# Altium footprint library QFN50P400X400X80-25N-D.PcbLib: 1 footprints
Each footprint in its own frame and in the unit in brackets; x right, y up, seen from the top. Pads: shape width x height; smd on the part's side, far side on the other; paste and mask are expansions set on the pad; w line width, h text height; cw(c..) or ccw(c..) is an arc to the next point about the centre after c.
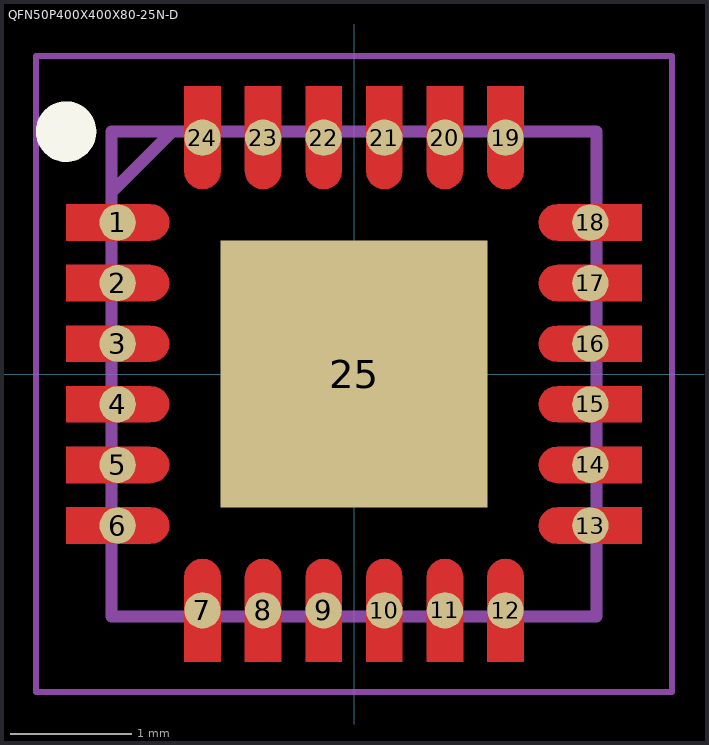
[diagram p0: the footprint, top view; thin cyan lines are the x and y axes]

## QFN50P400X400X80-25N-D [mm]
pads (25):
  round 0.3 smd: 1(-1.95,1.25) 2(-1.95,0.75) 3(-1.95,0.25) 4(-1.95,-0.25) 5(-1.95,-0.75) 6(-1.95,-1.25) 7(-1.25,-1.95) 8(-0.75,-1.95) 9(-0.25,-1.95) 10(0.25,-1.95) 11(0.75,-1.95) 12(1.25,-1.95) 13(1.95,-1.25) 14(1.95,-0.75) 15(1.95,-0.25) 16(1.95,0.25) 17(1.95,0.75) 18(1.95,1.25) 19(1.25,1.95) 20(0.75,1.95) 21(0.25,1.95) 22(-0.25,1.95) 23(-0.75,1.95) 24(-1.25,1.95)
  rect 2.2x2.2 smd: 25(0,0)
L1-Top Layer:
  region: -2.375,1.4 -1.675,1.4 -1.636,1.395 -1.6,1.38 -1.569,1.356 -1.545,1.325 -1.53,1.289 -1.525,1.25 -1.53,1.211 -1.545,1.175 -1.569,1.144 -1.6,1.12 -1.636,1.105 -1.675,1.1 -2.375,1.1
  region: -2.375,0.9 -1.675,0.9 -1.636,0.895 -1.6,0.88 -1.569,0.856 -1.545,0.825 -1.53,0.789 -1.525,0.75 -1.53,0.711 -1.545,0.675 -1.569,0.644 -1.6,0.62 -1.636,0.605 -1.675,0.6 -2.375,0.6
  region: -2.375,0.4 -1.675,0.4 -1.636,0.395 -1.6,0.38 -1.569,0.356 -1.545,0.325 -1.53,0.289 -1.525,0.25 -1.53,0.211 -1.545,0.175 -1.569,0.144 -1.6,0.12 -1.636,0.105 -1.675,0.1 -2.375,0.1
  region: -2.375,-0.1 -1.675,-0.1 -1.636,-0.105 -1.6,-0.12 -1.569,-0.144 -1.545,-0.175 -1.53,-0.211 -1.525,-0.25 -1.53,-0.289 -1.545,-0.325 -1.569,-0.356 -1.6,-0.38 -1.636,-0.395 -1.675,-0.4 -2.375,-0.4
  region: -2.375,-0.6 -1.675,-0.6 -1.636,-0.605 -1.6,-0.62 -1.569,-0.644 -1.545,-0.675 -1.53,-0.711 -1.525,-0.75 -1.53,-0.789 -1.545,-0.825 -1.569,-0.856 -1.6,-0.88 -1.636,-0.895 -1.675,-0.9 -2.375,-0.9
  region: -2.375,-1.1 -1.675,-1.1 -1.636,-1.105 -1.6,-1.12 -1.569,-1.144 -1.545,-1.175 -1.53,-1.211 -1.525,-1.25 -1.53,-1.289 -1.545,-1.325 -1.569,-1.356 -1.6,-1.38 -1.636,-1.395 -1.675,-1.4 -2.375,-1.4
  region: -1.4,-2.375 -1.4,-1.675 -1.395,-1.636 -1.38,-1.6 -1.356,-1.569 -1.325,-1.545 -1.289,-1.53 -1.25,-1.525 -1.211,-1.53 -1.175,-1.545 -1.144,-1.569 -1.12,-1.6 -1.105,-1.636 -1.1,-1.675 -1.1,-2.375
  region: -0.9,-2.375 -0.9,-1.675 -0.895,-1.636 -0.88,-1.6 -0.856,-1.569 -0.825,-1.545 -0.789,-1.53 -0.75,-1.525 -0.711,-1.53 -0.675,-1.545 -0.644,-1.569 -0.62,-1.6 -0.605,-1.636 -0.6,-1.675 -0.6,-2.375
  region: -0.4,-2.375 -0.4,-1.675 -0.395,-1.636 -0.38,-1.6 -0.356,-1.569 -0.325,-1.545 -0.289,-1.53 -0.25,-1.525 -0.211,-1.53 -0.175,-1.545 -0.144,-1.569 -0.12,-1.6 -0.105,-1.636 -0.1,-1.675 -0.1,-2.375
  region: 0.1,-2.375 0.1,-1.675 0.105,-1.636 0.12,-1.6 0.144,-1.569 0.175,-1.545 0.211,-1.53 0.25,-1.525 0.289,-1.53 0.325,-1.545 0.356,-1.569 0.38,-1.6 0.395,-1.636 0.4,-1.675 0.4,-2.375
  region: 0.6,-2.375 0.6,-1.675 0.605,-1.636 0.62,-1.6 0.644,-1.569 0.675,-1.545 0.711,-1.53 0.75,-1.525 0.789,-1.53 0.825,-1.545 0.856,-1.569 0.88,-1.6 0.895,-1.636 0.9,-1.675 0.9,-2.375
  region: 1.1,-2.375 1.1,-1.675 1.105,-1.636 1.12,-1.6 1.144,-1.569 1.175,-1.545 1.211,-1.53 1.25,-1.525 1.289,-1.53 1.325,-1.545 1.356,-1.569 1.38,-1.6 1.395,-1.636 1.4,-1.675 1.4,-2.375
  region: 2.375,-1.4 1.675,-1.4 1.636,-1.395 1.6,-1.38 1.569,-1.356 1.545,-1.325 1.53,-1.289 1.525,-1.25 1.53,-1.211 1.545,-1.175 1.569,-1.144 1.6,-1.12 1.636,-1.105 1.675,-1.1 2.375,-1.1
  region: 2.375,-0.9 1.675,-0.9 1.636,-0.895 1.6,-0.88 1.569,-0.856 1.545,-0.825 1.53,-0.789 1.525,-0.75 1.53,-0.711 1.545,-0.675 1.569,-0.644 1.6,-0.62 1.636,-0.605 1.675,-0.6 2.375,-0.6
  region: 2.375,-0.4 1.675,-0.4 1.636,-0.395 1.6,-0.38 1.569,-0.356 1.545,-0.325 1.53,-0.289 1.525,-0.25 1.53,-0.211 1.545,-0.175 1.569,-0.144 1.6,-0.12 1.636,-0.105 1.675,-0.1 2.375,-0.1
  region: 2.375,0.1 1.675,0.1 1.636,0.105 1.6,0.12 1.569,0.144 1.545,0.175 1.53,0.211 1.525,0.25 1.53,0.289 1.545,0.325 1.569,0.356 1.6,0.38 1.636,0.395 1.675,0.4 2.375,0.4
  region: 2.375,0.6 1.675,0.6 1.636,0.605 1.6,0.62 1.569,0.644 1.545,0.675 1.53,0.711 1.525,0.75 1.53,0.789 1.545,0.825 1.569,0.856 1.6,0.88 1.636,0.895 1.675,0.9 2.375,0.9
  region: 2.375,1.1 1.675,1.1 1.636,1.105 1.6,1.12 1.569,1.144 1.545,1.175 1.53,1.211 1.525,1.25 1.53,1.289 1.545,1.325 1.569,1.356 1.6,1.38 1.636,1.395 1.675,1.4 2.375,1.4
  region: 1.4,2.375 1.4,1.675 1.395,1.636 1.38,1.6 1.356,1.569 1.325,1.545 1.289,1.53 1.25,1.525 1.211,1.53 1.175,1.545 1.144,1.569 1.12,1.6 1.105,1.636 1.1,1.675 1.1,2.375
  region: 0.9,2.375 0.9,1.675 0.895,1.636 0.88,1.6 0.856,1.569 0.825,1.545 0.789,1.53 0.75,1.525 0.711,1.53 0.675,1.545 0.644,1.569 0.62,1.6 0.605,1.636 0.6,1.675 0.6,2.375
  region: 0.4,2.375 0.4,1.675 0.395,1.636 0.38,1.6 0.356,1.569 0.325,1.545 0.289,1.53 0.25,1.525 0.211,1.53 0.175,1.545 0.144,1.569 0.12,1.6 0.105,1.636 0.1,1.675 0.1,2.375
  region: -0.1,2.375 -0.1,1.675 -0.105,1.636 -0.12,1.6 -0.144,1.569 -0.175,1.545 -0.211,1.53 -0.25,1.525 -0.289,1.53 -0.325,1.545 -0.356,1.569 -0.38,1.6 -0.395,1.636 -0.4,1.675 -0.4,2.375
  region: -0.6,2.375 -0.6,1.675 -0.605,1.636 -0.62,1.6 -0.644,1.569 -0.675,1.545 -0.711,1.53 -0.75,1.525 -0.789,1.53 -0.825,1.545 -0.856,1.569 -0.88,1.6 -0.895,1.636 -0.9,1.675 -0.9,2.375
  region: -1.1,2.375 -1.1,1.675 -1.105,1.636 -1.12,1.6 -1.144,1.569 -1.175,1.545 -1.211,1.53 -1.25,1.525 -1.289,1.53 -1.325,1.545 -1.356,1.569 -1.38,1.6 -1.395,1.636 -1.4,1.675 -1.4,2.375
Top Overlay:
  circle w0.25: c-2.375,2 r0.125
Mechanical 15:
  lines w0.1: -2,1.5 -1.5,2 ; -2,-2 2,-2 2,2 -2,2 -2,-2
Mechanical 20:
  lines w0.05: -2.625,-2.625 2.625,-2.625 2.625,2.625 -2.625,2.625 -2.625,-2.625
3D body "ADP5587ACPZ-R7.stp": height 5.8, standoff -4.65, extent -10,-3.376 10,3.376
